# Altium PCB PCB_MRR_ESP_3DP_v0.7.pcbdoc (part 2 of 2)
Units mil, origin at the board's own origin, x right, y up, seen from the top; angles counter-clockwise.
Board outline 5100 x 5040 mil, 2 copper layers (Top Layer, Bottom Layer); 131 components, 154 nets, 480 pads, 79 vias.
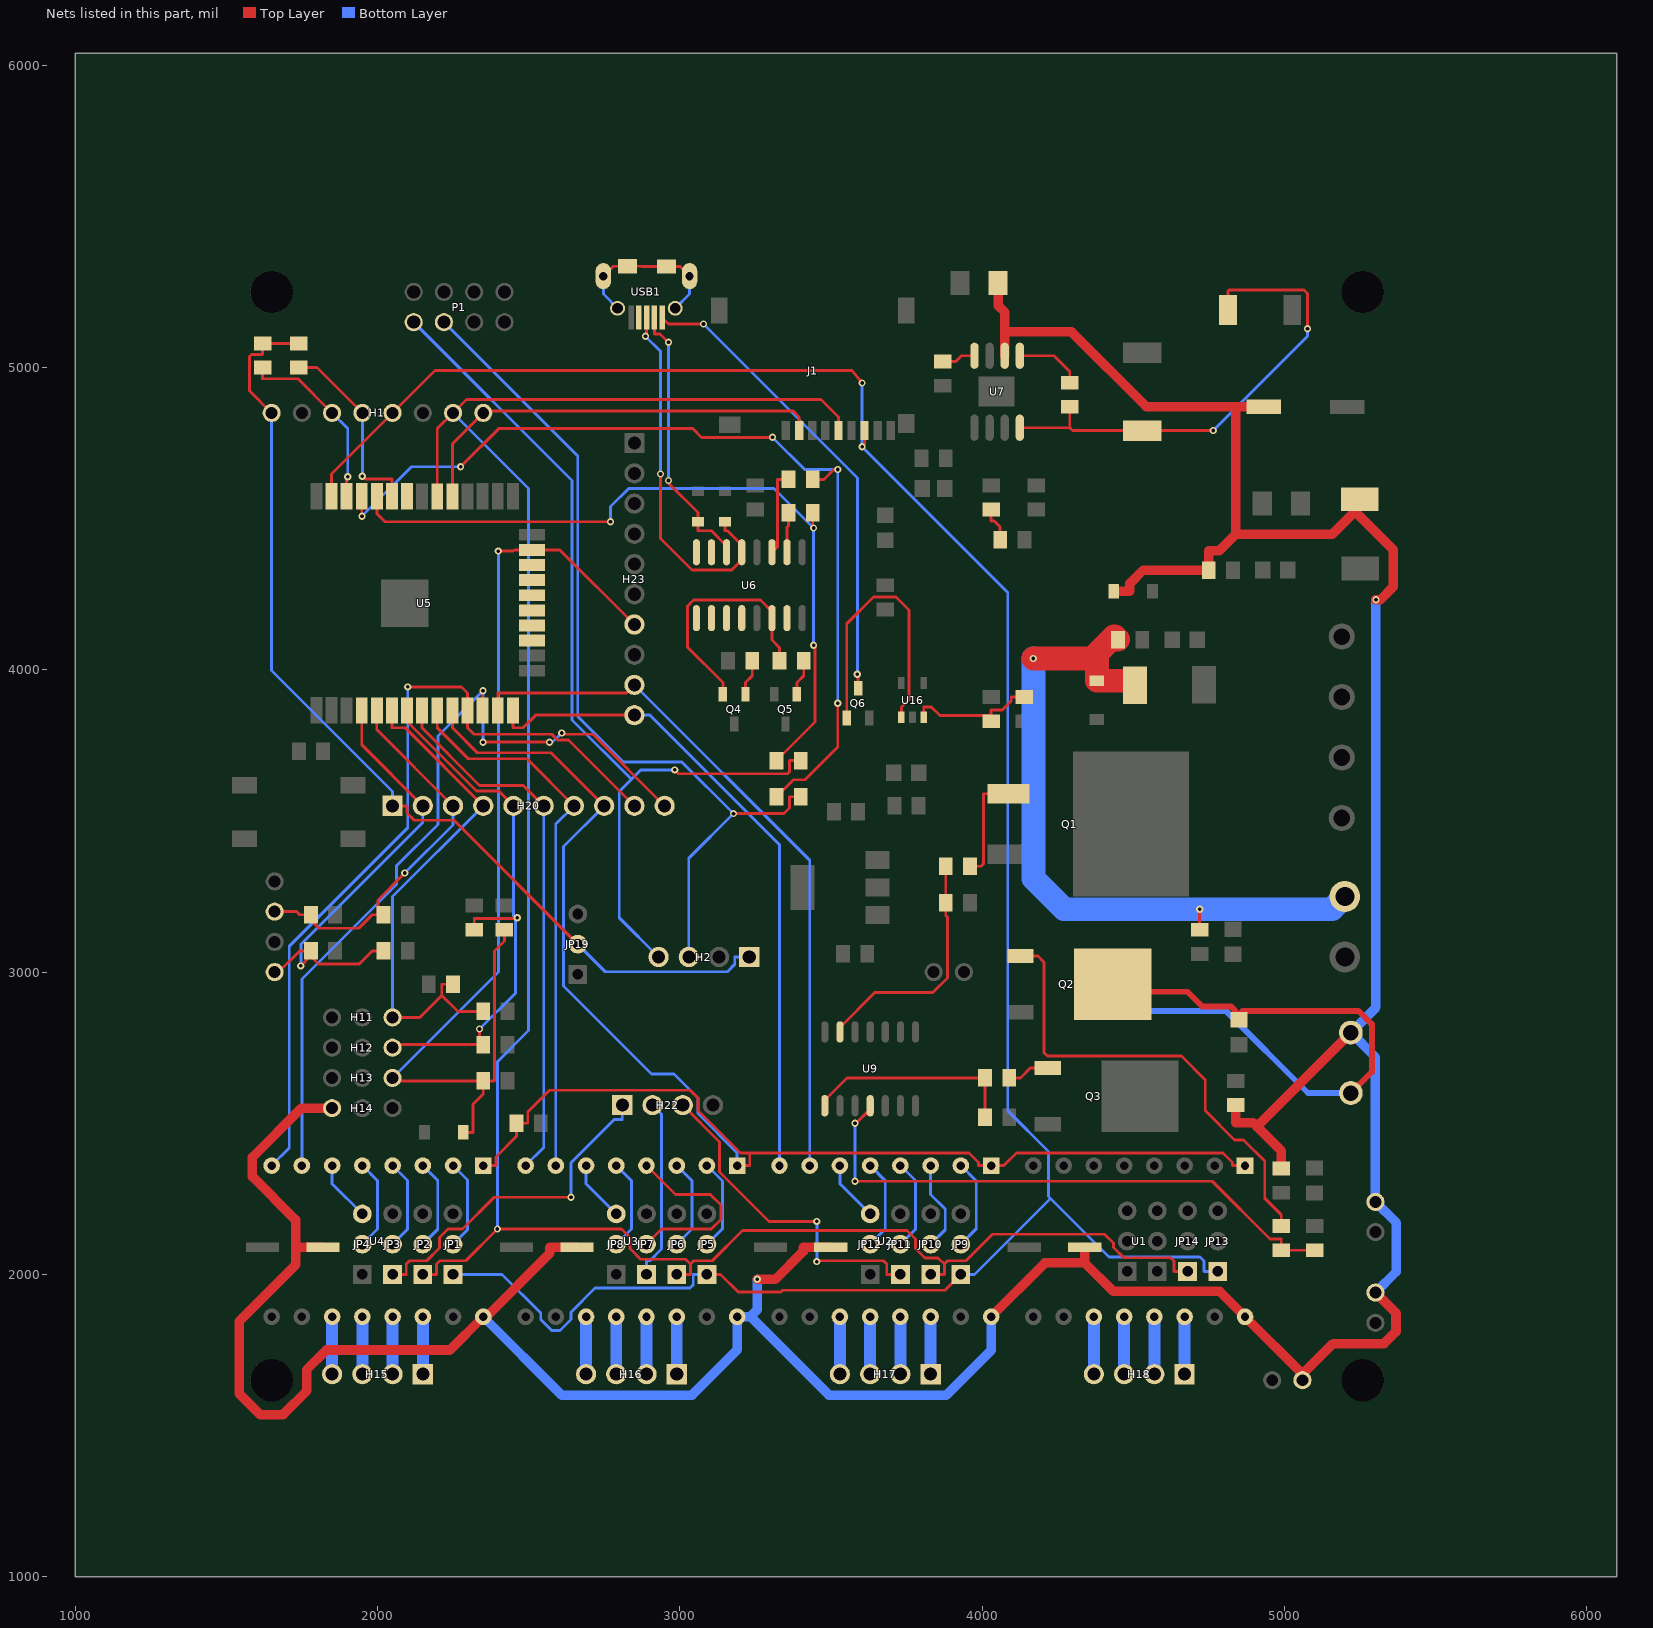
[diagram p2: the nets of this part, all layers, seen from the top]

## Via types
v1: diameter 24.02, hole 12.2, Top Layer to Bottom Layer, 62 vias
v2: diameter 24.4, hole 12, Top Layer to Bottom Layer, 17 vias

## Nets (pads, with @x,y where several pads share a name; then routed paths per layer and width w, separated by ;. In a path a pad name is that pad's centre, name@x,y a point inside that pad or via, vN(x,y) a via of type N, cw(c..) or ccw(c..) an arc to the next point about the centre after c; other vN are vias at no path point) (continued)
MOSI: H1.5 J1.7 JP1.1 JP5.1 JP9.1 JP13.1 U5.37 | length 8005.4
  Top Layer w9.45: U5.37@1848.1,4574.1 1848.1,4648.1 H1.5@2050,4850 2190,4990 3570,4990 v1(3603.3,4949) ; JP5.1@3090,2000 3135.3,2000 3193.4,1941.9 3335.2,1941.9 3340.7,1947.4 3877.4,1947.4 JP9.1@3930,2000 ; v1(3603.3,4737.9) 3610.6,4745.2 3611,4745.2 J1.7@3611,4791
  Bottom Layer w9.45: JP1.1@2250,2000 2295.3,2000 2412,2000 2540,1871.9 2540,1850.6 2576.7,1813.9 2603.4,1813.9 2640,1850.5 2640,1874.6 2720.2,1954.7 3033.4,1954.7 3044.7,1966 3044.7,2000 JP5.1@3090,2000 ; v1(3603.3,4949) v1(3603.3,4737.9) 4085.1,4256.2 4085.1,2541.4 4220,2406.5 4220,2257.6 4226.4,2251.1 ; JP9.1@3930,2000 3975.3,2000 4226.4,2251.1 ; JP13.1@4780,2010 4734.7,2010 4734.7,2043.9 4721.4,2057.3 4420.3,2057.3 4226.4,2251.1
MOTOR_EN_PIN: H20.8 R26.1 U1.1 U2.1 U3.1 U4.1 U5.10 | length 5138.2
  Top Layer w9.45: U5.10@2247.8,3865.8 2247.8,3808.2 2330.1,3725.9 2574.1,3725.9 H20.8@2750,3550 ; U4.1@2350,2360 2391.8,2360 2391.8,2388.6 2460,2456.8 2460,2495.2 R26.1@2460,2500 2497.1,2500 2497.1,2537.1 2569,2609 3034.3,2609 3060,2583.3 3060,2542.5 3200.8,2401.8 3231.8,2401.8 ; U3.1@3190,2360 3231.8,2360 3231.8,2401.8 ; U1.1@4870,2360 4828.2,2360 4828.2,2370.4 4796.9,2401.8 4113.5,2401.8 4071.8,2360 U2.1@4030,2360 3988.2,2360 3988.2,2370.4 3956.9,2401.8 3231.8,2401.8
  Bottom Layer w9.45: H20.8@2750,3550 2615.2,3415.2 2615.2,2954.4 2907.1,2662.5 2980.7,2662.5 3060,2583.2 3060,2531.8 3190,2401.8 U3.1@3190,2360
Q2_1: Q2.1 R7.2 | length 1561.1
  Top Layer w9.45: Q2.1@4127.4,3053 4185,3053 4205.5,3032.4 4205.5,2733.2 4216.3,2722.4 4659.6,2722.4 4738.6,2643.4 4738.6,2541.9 4835.7,2444.8 4865.2,2444.8 4935.2,2374.8 4935.2,2251.9 4990,2197.1 R7.2@4990,2159.9
Q2_4: LED6.2 P7.1 Q2.4 | length 2134
  Top Layer w19.68: Q2.4@4432.7,2960 4432.7,2942.3 4440,2935 4679.6,2935 4727.9,2886.7 4823.3,2886.7 LED6.2@4850.1,2859.9 ; LED6.2@4850.1,2842 LED6.2@4850.1,2859.9 ; P7.1@5220,2600 5289.7,2669.7 5289.7,2827.9 5245.9,2871.6 4861.7,2871.6 LED6.2@4850.1,2859.9
  Bottom Layer w19.68: 4437.5,2950 4515.8,2871.7 4806.7,2871.7 5078.3,2600 P7.1@5220,2600
Q4_1: Q4.1 R19.2 | length 120.2
  Top Layer w9.45: Q4.1@3217.4,3919.2 3217.4,3958.1 3240,3980.7 R19.2@3240,4030
Q5_1: Q5.1 R18.2 | length 120.2
  Top Layer w9.45: Q5.1@3387.4,3919.2 3387.4,3958.1 3410,3980.7 R18.2@3410,4030
R5_2: Q1.1 R5.2 | length 363.3
  Top Layer w9.45: R5.2@3960,3350 3997.1,3350 4004.3,3357.3 4004.3,3590 Q1.1@4087.5,3590
R9_2: Q3.1 R9.2 | length 141.2
  Top Layer w9.45: R9.2@4089.95,2650 4127.1,2650 4127.1,2650.2 4159.8,2683 Q3.1@4217.4,2683
R31_1: C9.1 R31.1 | length 118.5
  Top Layer w9.45: R31.1@4030,4530 4030,4492.9 4040.3,4492.9 4060,4473.2 C9.1@4060,4430
RTS: Q4.2 R18.1 U6.14 | length 815.9
  Top Layer w9.45: Q4.2@3142.6,3919.2 3142.6,3958.1 3025.8,4074.9 3025.8,4210.5 3045.9,4230.7 3266.8,4230.7 3305,4192.4 U6.14@3305,4171 3305,4098.2 3330,4073.2 3330,4051.6 3330,4045.4 R18.1@3330,4030
RX: R17.2 R28.1 U5.34 | length 2518.4
  Top Layer w9.45: U5.34@1998,4574 1998,4516.4 2024.7,4489.7 v1(2771.1,4489.7) ; R28.1@3320,3700 3447.1,3827.1 3447.1,4077.4 v1(3442.8,4081.7) ; R17.2@3440,4520 3440,4476.8 3442.8,4474 v1(3442.8,4469.1)
  Bottom Layer w9.45: v1(2771.1,4489.7) 2771.1,4539.9 2831.2,4600 3311.9,4600 v1(3442.8,4469.1) v1(3442.8,4081.7)
RXD: H2.4 P1.8 R28.2 | length 3086.7
  Top Layer w9.45: v1(2983.6,3669) 2996.3,3656.3 3356.3,3656.3 3362.9,3662.9 3362.9,3700 R28.2@3400,3700
  Bottom Layer w9.45: P1.8@2120,5150 2643.4,4626.6 2643.4,3834.5 2840.1,3637.8 ; H2.4@2930,3050 2800,3180 2800,3597.7 2840.1,3637.8 ; v1(2983.6,3669) 2871.2,3669 2840.1,3637.8
S$12: 
S$15: 
S$17: 
S$18: 
S$20: 
S$26: 
S$28: 
S$39: 
S$41: 
S$43: 
S$91: 
S$93: 
S$150: 
S$152: 
S$180: 
S$236: 
S$240: 
SCK: H1.7 J1.5 JP2.1 JP6.1 JP10.1 JP14.1 U5.30 | length 7577.6
  Top Layer w9.45: JP2.1@2150,2000 2195.3,2000 2195.3,2033.9 2206.6,2045.3 2292.1,2045.3 v1(2396.8,2150) 2807,2150 2835.3,2121.7 2835.3,2085.3 2870.6,2050 3019.2,2050 3035.3,2033.9 ; U5.30@2197.9,4573.9 2197.9,4797.9 H1.7@2250,4850 2294.3,4894.3 3467.4,4894.3 3525,4836.8 J1.5@3525,4791 ; JP6.1@2990,2000 3035.3,2000 3035.3,2033.9 ; JP10.1@3830,2000 3835,2000 3852.6,2000 3875.3,2000 3875.3,2033.9 ; JP14.1@4680,2010 4634.7,2010 4634.7,2043.9 4623.4,2055.3 4468.7,2055.3 4434.7,2089.2 4434.7,2103.4 4405.2,2133 4034.5,2133 3946.8,2045.3 3886.6,2045.3 3875.3,2033.9 ; 3035.3,2033.9 3046.6,2045.3 3107.5,2045.3 3207.5,2145.3 3751.8,2145.3 3780,2117 3780,2085.9 3811.1,2054.7 3854.5,2054.7 3875.3,2033.9
  Bottom Layer w9.45: H1.7@2250,4850 2500,4600 2500,2806.8 2396.9,2703.7 2396.9,2150 v1(2396.8,2150)
SCL: H1.3 R20.1 U5.36 | length 612.8
  Top Layer w9.45: R20.1@1620,5000 1620,4962.9 1737.1,4962.9 H1.3@1850,4850 ; U5.36@1898,4574 1898,4635.5 v1(1901.6,4639)
  Bottom Layer w9.45: H1.3@1850,4850 1901.6,4798.4 v1(1901.6,4639)
SDA: H1.4 R21.1 U5.33 | length 641.1
  Top Layer w9.45: R21.1@1740,5000 1800,5000 H1.4@1950,4850 ; v1(1950,4640.1) 1958.6,4631.6 2048,4631.6 U5.33@2048,4574
  Bottom Layer w9.45: v1(1950,4640.1) H1.4@1950,4850
SS: H1.8 J1.2 U5.29 | length 1419.7
  Top Layer w9.45: U5.29@2247.9,4573.9 2247.9,4747.9 H1.8@2350,4850 2356.1,4856.1 3375.7,4856.1 3395,4836.8 J1.2@3395,4791
TEMP_BED_PIN: C6.1 H10.1 H20.3 R12.1 U5.5 | length 1303.2
  Top Layer w9.45: H10.1@1660,3200 1732.9,3200 1742.9,3190 C6.1@1761.5,3190 ; C6.1@1780,3190 C6.1@1761.5,3190 ; U5.5@1997.9,3865.9 1997.9,3802.1 H20.3@2250,3550 ; R12.1@2020,3190 R12.1@2001.5,3190 ; v1(2090.4,3327.6) 2001.5,3238.7 R12.1@2001.5,3190 ; C6.1@1761.5,3190 1806.5,3145 1937.9,3145 1982.9,3190 R12.1@2001.5,3190
  Bottom Layer w9.45: v1(2090.4,3327.6) 2250,3487.2 H20.3@2250,3550
TEMP_E0_PIN: C5.1 H9.1 H20.2 R11.1 U5.4 | length 1585
  Top Layer w9.45: H9.1@1660,3000 1672.9,3000 1742.9,3070 C5.1@1761.5,3070 ; v1(1746.5,3020.6) C5.1@1778.7,3052.8 ; C5.1@1780,3070 C5.1@1761.5,3070 ; U5.4@1947.9,3865.9 1947.9,3752.1 H20.2@2150,3550 ; R11.1@2020,3070 1982.9,3070 1939.8,3026.8 1804.6,3026.8 C5.1@1778.7,3052.8 ; C5.1@1761.5,3070 C5.1@1778.7,3052.8
  Bottom Layer w9.45: v1(1746.5,3020.6) 1746.5,3091.2 2150,3494.7 H20.2@2150,3550
TO_E0: R7.1 R8.1 U9.11 | length 1908.9
  Top Layer w9.45: v1(3580,2308.1) 4761.8,2308.1 4952.9,2117.1 4990,2117.1 4990,2079.9 R8.1@5100,2079.9 ; v1(3580,2500) 3583.4,2500 3630,2546.6 U9.11@3630,2558
  Bottom Layer w9.45: v1(3580,2308.1) v1(3580,2500)
TO_FAN_E0: R9.1 R10.1 U9.8 | length 709.2
  Top Layer w9.45: U9.8@3480,2558 3480,2576.9 3553.1,2650 R9.1@4009.95,2650 R10.1@4009.95,2520
TO_HEAT_BED: R5.1 R6.1 U9.6 | length 809.9
  Top Layer w9.45: U9.6@3530,2802 3530,2817.1 3645.3,2932.4 3837.1,2932.4 3885.5,2980.8 3885.5,3181.4 3880,3186.8 R6.1@3880,3230 R5.1@3880,3350
TX: R16.2 R27.1 U5.35 | length 3100
  Top Layer w9.45: U5.35@1948,4574 1948,4509.5 v1(1949,4508.4) ; v1(2275.1,4671.7) 2401.2,4797.8 3043.5,4797.8 3072.1,4769.1 v1(3306.9,4769.1) ; R27.1@3320,3580 3376.3,3636.3 3414.3,3636.3 3522.5,3744.5 v1(3522.5,3889.7) ; R16.2@3440,4630 3477.1,4630 3509.6,4662.5 v1(3522.5,4662.5)
  Bottom Layer w9.45: v1(1949,4508.4) 2112.3,4671.7 v1(2275.1,4671.7) ; v1(3306.9,4769.1) 3413.5,4662.5 v1(3522.5,4662.5) v1(3522.5,3889.7)
TXD: H2.3 P1.6 R27.2 | length 2938.5
  Top Layer w9.45: v1(3177.7,3524.4) 3344.4,3524.4 3362.9,3542.9 3362.9,3580 R27.2@3400,3580
  Bottom Layer w9.45: P1.6@2220,5150 2662.4,4707.6 2662.4,3845.9 2813,3695.2 3006.9,3695.2 v1(3177.7,3524.4) 3030,3376.8 H2.3@3030,3050
U1_11: H18.4 U1.11 | length 190
  Bottom Layer w39.37: H18.4@4370,1670 U1.11@4370,1860
U1_12: H18.3 U1.12 | length 190
  Bottom Layer w39.37: H18.3@4470,1670 U1.12@4470,1860
U1_13: H18.2 U1.13 | length 190
  Bottom Layer w39.37: H18.2@4570,1670 U1.13@4570,1860
U1_14: H18.1 U1.14 | length 190
  Bottom Layer w39.37: H18.1@4670,1670 U1.14@4670,1860
U2_11: H17.4 U2.11 | length 190
  Bottom Layer w39.37: H17.4@3530,1670 U2.11@3530,1860
U2_12: H17.3 U2.12 | length 190
  Bottom Layer w39.37: H17.3@3630,1670 U2.12@3630,1860
U2_13: H17.2 U2.13 | length 190
  Bottom Layer w39.37: H17.2@3730,1670 U2.13@3730,1860
U2_14: H17.1 U2.14 | length 190
  Bottom Layer w39.37: H17.1@3830,1670 U2.14@3830,1860
U3_11: H16.4 U3.11 | length 190
  Bottom Layer w39.37: H16.4@2690,1670 U3.11@2690,1860
U3_12: H16.3 U3.12 | length 190
  Bottom Layer w39.37: H16.3@2790,1670 U3.12@2790,1860
U3_13: H16.2 U3.13 | length 190
  Bottom Layer w39.37: H16.2@2890,1670 U3.13@2890,1860
U3_14: H16.1 U3.14 | length 190
  Bottom Layer w39.37: H16.1@2990,1670 U3.14@2990,1860
U4_11: H15.4 U4.11 | length 190
  Bottom Layer w39.37: H15.4@1850,1670 U4.11@1850,1860
U4_12: H15.3 U4.12 | length 190
  Bottom Layer w39.37: H15.3@1950,1670 U4.12@1950,1860
U4_13: H15.2 U4.13 | length 190
  Bottom Layer w39.37: H15.2@2050,1670 U4.13@2050,1860
U4_14: H15.1 U4.14 | length 190
  Bottom Layer w39.37: H15.1@2150,1670 U4.14@2150,1860
U5_17: U5.17
U5_18: U5.18
U5_19: U5.19
U5_20: U5.20
U5_21: U5.21
U5_22: U5.22
U5_32: U5.32
U6_2: R17.1 U6.2 | length 133.1
  Top Layer w9.45: U6.2@3355,4389 3355,4471.8 3360,4476.8 R17.1@3360,4520
U6_3: R16.1 U6.3 | length 285.5
  Top Layer w9.45: U6.3@3305,4389 3322.9,4406.9 3322.9,4630 R16.1@3360,4630
U6_5: D5.1 U6.5 USB1.3 | length 1231.9
  Top Layer w9.45: v1(2887,5103.2) 2890.5,5106.7 USB1.3@2890.5,5165.1 ; v1(2936.3,4647.8) 2936.3,4435 3041.1,4330.2 3172.3,4330.2 3205,4362.9 U6.5@3205,4389 3205,4412.5 3157.5,4460 3150,4460 D5.1@3150,4490.05
  Bottom Layer w9.45: v1(2887,5103.2) 2936.3,5053.9 v1(2936.3,4647.8)
U6_6: D6.1 U6.6 USB1.2 | length 912.3
  Top Layer w9.45: USB1.2@2916,5165.1 2916,5111.4 2934.5,5111.4 v1(2962.6,5083.4) ; v1(2962.6,4626.4) 2962.6,4617.5 3060,4520.1 D6.1@3060,4490.05 3060,4460 3105,4460 3155,4410 U6.6@3155,4389
  Bottom Layer w9.45: v1(2962.6,4626.4) v1(2962.6,5083.4)
U6_7: U6.7
U6_8: U6.8
U6_9: U6.9
U6_10: U6.10
U6_11: U6.11
U6_12: U6.12
U6_15: U6.15
U7_1: C15.1 U7.1 | length 223.6
  Top Layer w9.45: U7.1@4125,5039 4238.1,5039 4290,4987.1 C15.1@4290,4950
U7_4: R32.1 U7.4 | length 112.9
  Top Layer w9.45: R32.1@3870,5020 3913.2,5020 3932.2,5039 U7.4@3975,5039
U7_8: C15.2 D4.2 L1.1 U7.8 | length 1628.1
  Top Layer w9.45: U7.8@4125,4801 4290,4801 ; C15.2@4290,4870 4290,4832.9 4290,4801 ; v1(4764.8,4791.6) D4.2@4530,4791.6 4299.4,4791.6 4290,4801 ; L1.1@4813.7,5190 4813.7,5253.5 4816.8,5256.6 5065.1,5256.6 5077,5244.7 v1(5077,5128)
  Bottom Layer w9.45: v1(4764.8,4791.6) 5077,5103.8 v1(5077,5128)
U16_1: Q6.1 U16.1 | length 937.3
  Top Layer w9.45: Q6.1@3552.6,3840.8 3552.6,3879.7 3552.6,4152.3 3641.5,4241.2 3715.1,4241.2 3758.2,4198.1 3758.2,3902.1 3733.1,3877 U16.1@3733.1,3843
U16_3: R23.1 R30.1 U16.3 | length 441.3
  Top Layer w9.45: U16.3@3807.1,3843 3807.1,3877 3832.2,3877 3860.6,3848.5 R23.1@4030,3848.5 ; R23.1@4030,3829.99 R23.1@4030,3848.5 ; R30.1@4140.01,3910 4096.8,3910 4096.8,3896.8 4067.1,3867.1 4030,3867.1 R23.1@4030,3848.5
USB1_0: USB1.0 | length 564.6
  Top Layer w9.45: USB1.0@2747.5,5302.31 2748.8,5302.3 2781.4,5334.9 USB1.0@2827.2,5334.9 2873,5334.9 2873.6,5334.2 USB1.0@2956.3,5334.25 2979.2,5334.2 3002.1,5334.2 3002.1,5332.7 USB1.0@3032.5,5302.31
  Bottom Layer w9.45: USB1.0@2747.5,5302.31 2747.5,5242.8 USB1.0@2794.3,5196.01 ; USB1.0@2984.9,5196.01 3032.5,5243.6 USB1.0@3032.5,5302.31
USB1_4: USB1.4
VBED: CN2.2 D2.2 F1.2 R3.1 R14.1 | length 2415.1
  Top Layer w9.45: R3.1@4720,3140 v2(4720,3208.3)
  Top Layer w78.74: v1(4169.8,4037.4) 4380,4037.4 ; R14.1@4450,4100 4439.5,4110.5 4436.3,4110.5 4380,4054.2 4380,4037.4 ; F1.2@4505.7,3949.5 4491.2,3964 D2.2@4380,3964 4380,4037.4
  Bottom Layer w78.74: v1(4169.8,4037.4) 4169.8,3310 4271.4,3208.3 v2(4720,3208.3) 5158.3,3208.3 CN2.2@5200,3250
VIN: C1.1 C2.1 C3.1 C4.1 C8.1 C14.1 D1.2 F2.2 H7.1 H8.1 H14.1 H19.1 P7.2 R1.1 R2.1 R13.1 U1.16 U2.16 U3.16 U4.16 U7.2 | length 13465.5
  Top Layer w31.5: C1.1@1820,2090 1729.4,2090 ; H14.1@1850,2550 1748.5,2550 1586.1,2387.6 1586.1,2323.9 1729.4,2180.6 1729.4,2090 ; C2.1@2660,2090 2569.4,2090 2569.4,2069.3 2360.2,1860 U4.16@2350,1860 2239.9,1749.9 1831.2,1749.9 1765.9,1684.5 1765.9,1614.5 1687.9,1536.5 1611.6,1536.5 1543.5,1604.5 1543.5,1845.4 1729.4,2031.3 1729.4,2090 ; v1(3256,1984) 3316.3,1984 3409.4,2077.2 3409.4,2090 C3.1@3500,2090 ; U2.16@4030,1860 4207.9,2037.8 4340,2037.8 ; C8.1@4052.99,5280 4053,5205.2 4075,5183.2 4075,5117.8 ; U7.2@4075,5039 4075,5117.8 ; C4.1@4340,2090 4340,2037.8 ; D1.2@4436,4260 4489.4,4260 4489.4,4286 4533.4,4330 R13.1@4750,4330 4750,4394.4 4785,4394.4 4839.6,4449 ; R1.1@4840,2560 4840,2501.7 4896.6,2501.7 4909.2,2489.1 ; C14.1@4932.2,4870.2 4839.6,4870.2 ; R2.1@4990.1,2350 4990.1,2408.3 4909.2,2489.1 ; H8.1@5060,1650 H8.1@5060,1670 ; P7.2@5220,2800 4909.2,2489.1 ; F2.2@5249.5,4564.3 5233.7,4548.6 5233.7,4523.7 ; H7.1@5301.5,1939.9 5369.5,1871.9 5369.5,1810.9 5330,1771.3 5161.3,1771.3 H8.1@5060,1670 ; v1(5303,4231.5) 5317.2,4231.5 5359.8,4274.1 5359.8,4397.7 5233.7,4523.7 ; 4075,5117.8 4296,5117.8 4543.5,4870.2 4839.6,4870.2 ; 4340,2037.8 4434.3,1943.5 4786.5,1943.5 U1.16@4870,1860 H8.1@5060,1670 ; 4839.6,4449 5159.1,4449 5233.7,4523.7 ; 4839.6,4449 4839.6,4870.2
  Bottom Layer w31.5: U4.16@2350,1860 2609,1601 3041.1,1601 3190,1750 U3.16@3190,1860 3233.6,1860 3233.9,1860.3 ; v1(3256,1984) 3256,1882.4 3233.9,1860.3 ; U2.16@4030,1860 4030,1748.5 3882.2,1600.7 3493.5,1600.7 3233.9,1860.3 ; H7.1@5301.5,1939.9 5370.3,2008.6 5370.3,2171.1 H19.1@5301.5,2239.9 5301.5,2718.5 P7.2@5220,2800 5303,2883 v1(5303,4231.5)
VOUT: H1.1 H2.1 H20.1 JP19.2 R20.2 R21.2 | length 3341
  Top Layer w9.45: H1.1@1650,4850 1576.8,4923.2 1576.8,5036.8 1582.9,5042.9 1620,5042.9 R20.2@1620,5080 R21.2@1740,5080 ; H20.1@2050,3550 2097.8,3550 2097.8,3526.1 2121.6,3502.2 2253,3502.2 JP19.2@2662.8,3092.4
  Bottom Layer w9.45: H1.1@1650,4850 1650,3997.8 2050,3597.8 H20.1@2050,3550 ; JP19.2@2662.8,3092.4 2753.8,3001.4 3157.5,3001.4 3182.2,3026.1 3182.2,3050 H2.1@3230,3050
VUSB: Q6.3 USB1.1 | length 1562.1
  Top Layer w9.45: USB1.1@2941.6,5165.1 2962.9,5143.8 v1(3078.4,5143.8) ; v1(3587.5,3985.7) 3587.5,3980.6 3590,3978.1 Q6.3@3590,3939.2
  Bottom Layer w9.45: v1(3078.4,5143.8) 3587.5,4634.7 v1(3587.5,3985.7)
X_CS: H22.1 JP3.1 | length 1126.9
  Top Layer w9.45: JP3.1@2050,2000 2095.3,2000 2095.3,2033.9 2106.6,2045.3 2163,2045.3 2204.7,2087 2204.7,2121.7 2233,2150 2281,2150 2386.1,2255.2 v1(2640,2255.2)
  Bottom Layer w9.45: v1(2640,2255.2) 2640,2369.1 2783.1,2512.2 2810,2512.2 H22.1@2810,2560
X_DIR_PIN: H20.9 U4.8 U5.11 | length 2750.5
  Top Layer w9.45: v1(2100,3943.6) 2277.6,3943.6 2297.8,3923.4 U5.11@2297.8,3865.8 2297.8,3837 2297.8,3808.2 2319.1,3786.9 2576.7,3786.9 2595.7,3767.9 2632.1,3767.9 H20.9@2850,3550
  Bottom Layer w9.45: U4.8@1650,2360 1708.2,2418.2 1708.2,3085.6 2100,3477.4 v1(2100,3943.6)
X_MIN: C11.1 H11.3 H20.4 R24.1 U5.6 | length 1717.2
  Top Layer w9.45: U5.6@2047.9,3865.9 2047.9,3808.3 2091.7,3808.3 H20.4@2350,3550 ; H11.3@2050,2850 2140,2850 2212.9,2922.9 ; C11.1@2250,2960 2212.9,2960 2212.9,2922.9 ; R24.1@2350,2870 2265.9,2870 2212.9,2922.9
  Bottom Layer w9.45: H11.3@2050,2850 2050,3250 H20.4@2350,3550
X_MS1: JP1.2 U4.2 | length 299.7
  Bottom Layer w9.45: JP1.2@2250,2100 2297.9,2147.9 2297.9,2312.1 U4.2@2250,2360
X_MS2: JP2.2 U4.3 | length 300.8
  Bottom Layer w9.45: JP2.2@2150,2100 2199.3,2149.3 2199.3,2310.7 U4.3@2150,2360
X_MS3: JP3.2 U4.4 | length 300.9
  Bottom Layer w9.45: JP3.2@2050,2100 2099.4,2149.4 2099.4,2310.6 U4.4@2050,2360
X_RST: JP4.2 U4.5 | length 301.4
  Bottom Layer w9.45: JP4.2@1950,2100 2000,2150 2000,2310 U4.5@1950,2360
X_SLP: JP4.3 U4.6 | length 201.4
  Bottom Layer w9.45: U4.6@1850,2360 1850,2300 JP4.3@1950,2200
X_STEP_PIN: H20.10 U4.7 U5.12 | length 2771.6
  Top Layer w9.45: U5.12@2347.9,3865.9 2347.9,3929.3 v1(2349.4,3930.8) ; v1(2349.4,3760.8) v1(2569.4,3760.8) ; v1@2603.6,3786.9 2713.1,3786.9 H20.10@2950,3550
  Bottom Layer w9.45: U4.7@1750,2360 1750,2977 2062.9,3289.9 2062.9,3351.7 2200,3488.8 2200,3781.4 v1(2349.4,3930.8) v1(2349.4,3760.8) ; v1(2569.4,3760.8) 2579.4,3760.8 v1(2609.4,3790.8)
Y_CS: H22.2 JP7.1 | length 599.8
  Bottom Layer w9.45: JP7.1@2890,2000 2890,2045.3 2901.3,2045.3 2940,2083.9 2940,2530 H22.2@2910,2560
Y_DIR_PIN: H20.6 U3.8 U5.8 | length 1781.6
  Top Layer w9.45: U5.8@2147.8,3865.8 2147.8,3808.2 2338.1,3617.9 2482.1,3617.9 H20.6@2550,3550
  Bottom Layer w9.45: U3.8@2490,2360 2550,2420 H20.6@2550,3550
Y_MIN: C12.1 H12.3 H20.5 R25.1 U5.7 | length 1838.1
  Top Layer w9.45: H12.3@2050,2750 2060,2760 2331.5,2760 R25.1@2337.8,2760 ; U5.7@2097.9,3865.9 2097.9,3829 2328,3598.9 2401.1,3598.9 H20.5@2450,3550 ; C12.1@2320,3140 2320,3177.1 2459.6,3177.1 v1(2462.8,3180.2) ; v1(2337.8,2811.8) R25.1@2337.8,2760 ; R25.1@2350,2760 R25.1@2337.8,2760
  Bottom Layer w9.45: v1(2337.8,2811.8) 2456.4,2930.3 v1@2456.4,3180.2 ; H20.5@2450,3550 2450,3186.6 v1@2456.4,3180.2 ; v1(2462.8,3180.2) v1@2456.4,3180.2
Y_MS1: JP5.2 U3.2 | length 302.3
  Bottom Layer w9.45: JP5.2@3090,2100 3141,2150.9 3141,2309 U3.2@3090,2360
Y_MS2: JP6.2 U3.3 | length 301.4
  Bottom Layer w9.45: JP6.2@2990,2100 3040,2150 3040,2310 U3.3@2990,2360
Y_MS3: JP7.2 U3.4 | length 627.5
  Top Layer w9.45: JP7.2@2890,2100 2940,2150 3104,2150 3136.1,2182.1 3136.1,2229.2 3101,2264.3 2985.7,2264.3 U3.4@2890,2360
Y_RST: JP8.2 U3.5 | length 301.4
  Bottom Layer w9.45: JP8.2@2790,2100 2840,2150 2840,2310 U3.5@2790,2360
Y_SLP: JP8.3 U3.6 | length 201.4
  Bottom Layer w9.45: U3.6@2690,2360 2690,2300 JP8.3@2790,2200
Y_STEP_PIN: H20.7 U3.7 U5.9 | length 1831.6
  Top Layer w9.45: U5.9@2197.8,3865.8 2197.8,3808.2 2300.3,3705.7 2494.3,3705.7 H20.7@2650,3550
  Bottom Layer w9.45: U3.7@2590,2360 2590,3490 H20.7@2650,3550
Z_CS: H22.3 JP11.1 | length 1110.4
  Top Layer w9.45: H22.3@3010,2560 3131.8,2438.2 3131.8,2339 3295.4,2175.4 v1(3453.6,2175.4) ; v1(3453.6,2042.3) 3456.5,2045.3 3673.4,2045.3 3684.7,2033.9 3684.7,2000 JP11.1@3730,2000
  Bottom Layer w9.45: v1(3453.6,2042.3) v1(3453.6,2175.4)
Z_DIR_PIN: H23.10 U2.8 U5.14 | length 2196
  Top Layer w9.45: U5.14@2447.9,3865.9 2447.9,3808.3 2481.9,3808.3 2523.5,3850 H23.10@2850,3850
  Bottom Layer w9.45: H23.10@2850,3850 2901.5,3850 3330,3421.5 U2.8@3330,2360
Z_MIN: C13.1 D3.2 H13.3 H23.7 R29.1 U5.23 | length 3512.8
  Top Layer w9.45: H13.3@2050,2650 2060,2640 R29.1@2350,2640 ; D3.2@2284,2470 2316.2,2470 2316.2,2563 2350,2596.8 R29.1@2350,2640 ; v1(2400,4392.8) 2449.4,4392.8 2453.4,4396.9 U5.23@2511,4396.9 2603.1,4396.9 H23.7@2850,4150 ; C13.1@2420,3140 2420,3102.9 2387.1,3070 2387.1,2640 2368.5,2640 R29.1@2350,2640
  Bottom Layer w9.45: H13.3@2050,2650 2400,3000 v1(2400,4392.8)
Z_MS1: JP9.2 U2.2 | length 302.3
  Bottom Layer w9.45: JP9.2@3930,2100 3981,2150.9 3981,2309 U2.2@3930,2360
Z_MS2: JP10.2 U2.3 | length 299.9
  Bottom Layer w9.45: JP10.2@3830,2100 3878.1,2148 3878.1,2216 3830,2264 U2.3@3830,2360
Z_MS3: JP11.2 U2.4 | length 300.9
  Bottom Layer w9.45: JP11.2@3730,2100 3779.4,2149.4 3779.4,2310.6 U2.4@3730,2360
Z_RST: JP12.2 U2.5 | length 301.4
  Bottom Layer w9.45: JP12.2@3630,2100 3680,2150 3680,2310 U2.5@3630,2360
Z_SLP: JP12.3 U2.6 | length 201.4
  Bottom Layer w9.45: U2.6@3530,2360 3530,2300 JP12.3@3630,2200
Z_STEP_PIN: H23.9 U2.7 U5.13 | length 2350.9
  Top Layer w9.45: U5.13@2397.9,3865.9 2397.9,3923.5 2823.5,3923.5 H23.9@2850,3950
  Bottom Layer w9.45: H23.9@2850,3950 3430,3370 U2.7@3430,2360
pads on no net: H3.1 H4.1 H5.1 H6.1 P1.5 P1.7 U5.39 U7.3 U7.9 U9.1 U9.2 U9.3
copper on no net:
  other v2: 1970,4110 2130,4110 2270,4110 1970,4220 2130,4220 2270,4220 1970,4340 2130,4340 2270,4340

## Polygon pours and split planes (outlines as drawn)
GND on Bottom Layer (solid): 4920,1730 4920,2410 3320,2430 3320,3120 3000,3130 3020,3620 2920,3630 2920,5110 3050,5120 3070,5470 5580,5440 5550,4210 5120,4127.02 5120,2470 5200,2480 5200,1770
GND on Bottom Layer (solid): 2600,3450 2600,2930 2740,2920 2740,2410 2130,2430 2120,2920 1740,2920 1740,3450
GND on Top Layer (solid): 5600,4240 5600,5500 3080,5540 3070,5080 2650,5100 2650,4810 2920,4820 2910,3610 3010,3610 3010,3110 3290,3130 3270,2430 4910,2400 4920,1760 5240,1800 5220,2480 5110,2480 5110,4200
GND on Top Layer (solid): 2750,2430 2740,2910 2570,2910 2620,3480 1720,3490 1720,2950 2120,2950 2150,2410

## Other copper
Top Layer:
  region net Q2_4: 4230,3120 4650,3120 4650,2750 4230,2750 4230,2840 4230,3000
  region: 1900,4020 1900,4430 2370,4430 2370,4020
  region net LED5_2: 4330,3730 5030,3730 5030,3210 4840,3200 4810,3250 4760,3250 4330,3250
  region net LED5_2: 4800,3240 4800,3120 4970,3120 4970,3000 5100,3000 5100,3350 5000,3350 5000,3240 4810,3230
  region net Q2_4: 4660,3000 4890,3000 5060,2930 5060,2810 4810,2810 4690,2810 4670,2790 4630,2790 4630,3000
Bottom Layer:
  region net LED5_2: 4300,3280 4290,3380 4290,3620 4300,3730 4690,3730 4740,3730 4930,3730 5030,3730 5030,3280
  region net Q2_4: 4220,3120 4650,3120 4650,2780 4230,2780 4230,2870 4230,3030
  region: 1900,4020 1900,4430 2370,4430 2370,4020
  region net LED7_2: 4210,2640 4700,2640 4700,2460 4210,2460
  region net Q2_4: 4660,3000 4990,3000 4990,2820 4980,2810 4700,2810 4650,2790 4610,2810 4620,3000

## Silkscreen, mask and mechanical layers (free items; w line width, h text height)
Top Overlay:
  text "TF_Card" at 3380,5004.97 h33.46
  text "IO5" at 2369.68,4930 h39.37 r90
  text "GND" at 2670,4718.81 h39.37
  text "SS" at 2369.68,4710 h39.37 r90
  text "GND" at 1769.68,4670 h39.37 r90
  text "SCL" at 1869.68,4670 h39.37 r90
  text "SDA" at 1969.68,4670 h39.37 r90
  text "SCK" at 2269.68,4670 h39.37 r90
  text "MOSI" at 2068.18,4650.6 h39.37 r90
  text "MISO" at 2168.18,4650.6 h39.37 r90
  text "Vout" at 1669.68,4649.66 h39.37 r89
  text "IO17" at 2670,4620.31 h39.37
  text "5V" at 3727.39,4576.13 h33.46 r86
  text "IO16" at 2670,4520.31 h39.37
  text "IO4" at 2690,4420.31 h39.37
  text "IO0" at 2690,4320.31 h39.37
  text "VIN" at 5069.71,4304.97 h33.46 r359
  text "IO2" at 2690,4220.31 h39.37
  text "VBED" at 4630,4154.97 h33.46
  text "IO15" at 2670,4120.31 h39.37
  text "VIN" at 4891.72,4063.48 h59.05 r89
  text "12-24V" at 4945.03,4045.1 h33.46 r90
  text "IO13" at 2670,4020.32 h39.37
  text "IO14" at 2670,3920.32 h39.37
  text "GND" at 4891.73,3859.1 h59.05 r90
  text "IO12" at 2670,3820.32 h39.37
  text "BOOT" at 1530,3668.82 h39.37
  text "3V" at 3838.54,3645.03 h33.46 r355
  text "VP" at 2169.64,3641.37 h39.37 r94
  text "VN" at 2269.68,3640 h39.37 r90
  text "IO34" at 2369.68,3640 h39.37 r90
  text "IO35" at 2469.68,3640 h39.37 r90
  text "IO32" at 2569.68,3640 h39.37 r90
  text "IO33" at 2661.18,3640 h39.37 r90
  text "IO25" at 2759.68,3640 h39.37 r90
  text "IO26" at 2869.68,3640 h39.37 r90
  text "IO27" at 2969.68,3640 h39.37 r90
  text "Vout" at 2069.68,3629.66 h39.37 r89
  text "12-24V" at 4946.73,3620 h33.46 r90
  text "VBED" at 4899.53,3610 h59.05 r90
  text "GND" at 4899.53,3430 h59.05 r90
  text "T_BED" at 1537.5,3370 h45 r270
  text "MRR_ESP_3DP" at 2170,3330.63 h78.74
  text "v0.7" at 3050,3330.63 h78.74
  text "Vout" at 3210.32,3260.34 h39.37 r269
  text "GND" at 3110.32,3240 h39.37 r270
  text "BED" at 4819.42,3213.6 h47.24 r90
  text "RX" at 2910.32,3210 h39.37 r270
  text "TX" at 3010.32,3210 h39.37 r270
  text "BED+" at 4951.73,3153.8 h59.05 r90
  text "3.3V" at 2596.73,3148.2 h33.46 r90
  text "T_E0" at 1537.5,3110 h45 r270
  text "MOS_EN" at 3780,3068.82 h39.37
  text "-" at 4930,3051.23 h59.05 r180
  text "Vout_SEL" at 2772.48,2962.74 h39.37 r91
  text "5V" at 2596.69,2958.83 h33.46 r86
  text "V  G  S" at 1840,2930.32 h39.37
  text "Licensed under CERN OHL v.1.2" at 2790,2900.32 h39.37
  text "E0" at 4799.42,2867.8 h47.24 r90
  text "X_MIN" at 2130,2830.32 h39.37
  text "E0+" at 4981.73,2733.8 h59.05 r90
  text "Y_MIN" at 2130,2730.32 h39.37
  text "Z_MIN" at 2129.66,2630.32 h39.37 r359
  text "-" at 4960,2599.53 h59.05 r180
  text "Z_PROBE" at 2130,2530.32 h39.37
  text "X  Y  Z  E0" at 2770,2426.38 h47.24
  text "PART / FAN" at 5282.69,2319.3 h39.37 r90
  text "RST" at 1910,2273.27 h33.46
  text "MS3" at 2010,2273.27 h33.46
  text "MS2" at 2120,2273.27 h33.46
  text "MS1" at 2230,2273.27 h33.46
  text "RST" at 2750,2273.27 h33.46
  text "MS3" at 2850,2273.27 h33.46
  text "MS2" at 2960,2273.27 h33.46
  text "MS1" at 3070,2273.27 h33.46
  text "RST" at 3580,2273.27 h33.46
  text "MS3" at 3680,2273.27 h33.46
  text "MS2" at 3790,2273.27 h33.46
  text "MS1" at 3900,2273.27 h33.46
  text "RST" at 4430,2273.27 h33.46
  text "MS3" at 4540,2273.27 h33.46
  text "MS2" at 4650,2273.27 h33.46
  text "MS1" at 4760,2273.27 h33.46
  text "+" at 5200.62,2270.78 h59.05 r225
  text "-" at 5201.5,2116.17 h59.05
  text "VMOT" at 2333.27,2030 h33.46 r270
  text "VMOT" at 3173.27,2030 h33.46 r270
  text "VMOT" at 4013.27,2030 h33.46 r270
  text "VMOT" at 4853.27,2030 h33.46 r270
  text "+" at 5200.62,1980.78 h59.05 r225
  text "TMC" at 4430,1913.27 h33.46
  text "SPI" at 4540,1913.27 h33.46
  text "SPI" at 4640,1913.27 h33.46
  text "SPI" at 4740,1913.27 h33.46
  text "TMC" at 1910,1903.27 h33.46
  text "SPI" at 2020,1903.27 h33.46
  text "SPI" at 2120,1903.27 h33.46
  text "SPI" at 2220,1903.27 h33.46
  text "TMC" at 2750,1903.27 h33.46
  text "SPI" at 2860,1903.27 h33.46
  text "SPI" at 2960,1903.27 h33.46
  text "SPI" at 3060,1903.27 h33.46
  text "TMC" at 3590,1903.27 h33.46
  text "SPI" at 3700,1903.27 h33.46
  text "SPI" at 3800,1903.27 h33.46
  text "SPI" at 3900,1903.27 h33.46
  text "-" at 5201.5,1820.37 h59.05
  text "E0 FAN" at 5161.19,1799.9 h39.37 r90
  text "-" at 4959.53,1760 h59.05 r90
  text "CASE / FAN" at 4770,1738.82 h39.37
  text "+" at 5050.88,1739.12 h59.05 r45
  text "X_MOTOR" at 1830.41,1550.58 h47.24 r1
  text "Y_MOTOR" at 2670.41,1546.38 h47.24 r1
  text "Z_MOTOR" at 3520,1546.38 h47.24
  text "E0_MOTOR" at 4360,1536.38 h47.24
